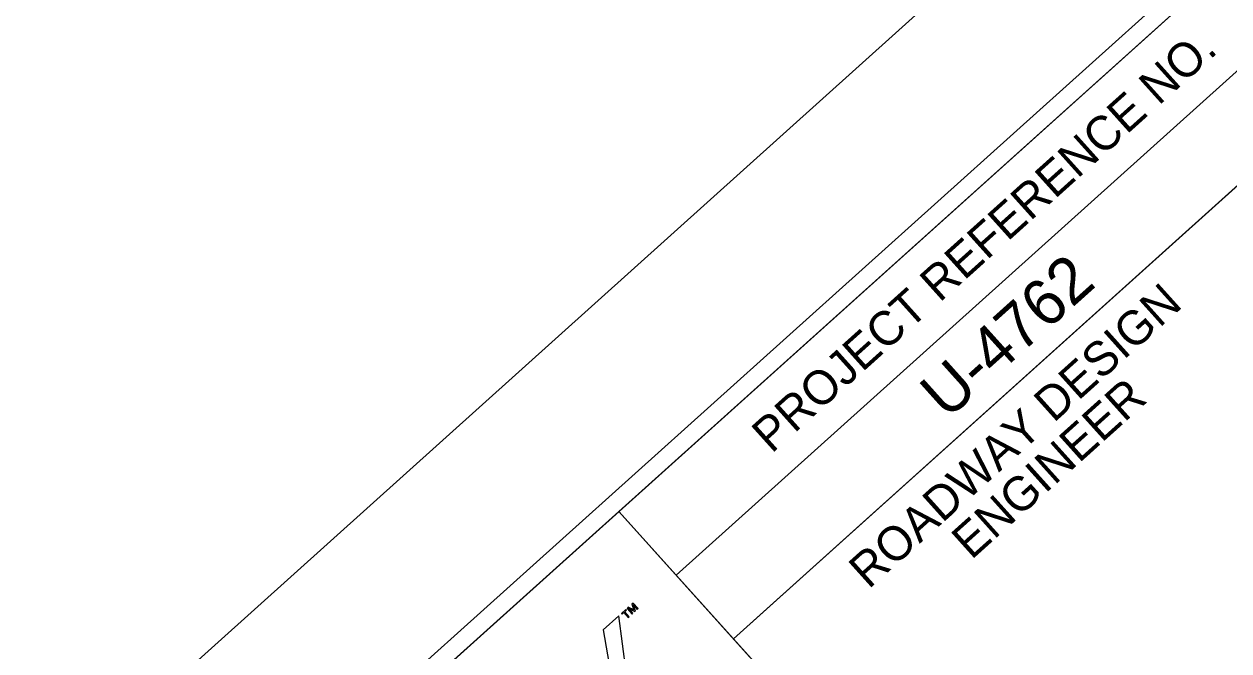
# Model space of a CAD drawing. Extents: x 2488411 to 2488707, y 383669 to 383962.
# Drawn here: x 2488591.42 to 2488612.58, y 383939.51 to 383950.52 of the extents above; entities that cross this region are included whole.
import ezdxf

# ---------------------------------------------------------------- set-up
doc = ezdxf.new("R2010")
doc.units = 0
for name, color, linetype in [('Old_Level_19', 7, 'Continuous'), ('Old_Level_21', 7, 'Continuous'), ('Prop XS SE Text', 7, 'Continuous'), ('Sheet Cutting Line CELL', 7, 'Continuous'), ('Sheet Plot Border Outside CELL', 7, 'Continuous'), ('Sheet Profile CELL', 7, 'Continuous'), ('Sheet Title CELL', 7, 'Continuous')]:
    doc.layers.add(name, color=color, linetype=linetype)

msp = doc.modelspace()

# ---------------------------------------------------------------- linework, layer by layer
at = {"layer": 'Old_Level_19'}
msp.add_lwpolyline([(2488619.231, 383961.604), (2488468.948, 383826.508), (2488557.194, 383728.341), (2488707.477, 383863.438)], close=True, dxfattribs=at)
at = {"layer": 'Old_Level_21'}
msp.add_lwpolyline([(2488620.631, 383959.24), (2488471.909, 383825.547), (2488556.553, 383731.388), (2488705.275, 383865.081)], close=True, dxfattribs=at)
at = {"layer": 'Prop XS SE Text'}
msp.add_line((2488619.231, 383961.604), (2488468.948, 383826.508), dxfattribs=at)
at = {"layer": 'Sheet Cutting Line CELL'}
msp.add_line((2488602.874, 383940.841), (2488620.726, 383956.89), dxfattribs=at)
for points in [[(2488619.72, 383958.009), (2488485.857, 383837.674), (2488570.092, 383743.97), (2488703.955, 383864.305)], [(2488601.867, 383941.961), (2488619.72, 383958.009), (2488621.729, 383955.774), (2488603.876, 383939.725)], [(2488603.876, 383939.725), (2488612.805, 383947.752), (2488621.83, 383937.712), (2488612.902, 383929.685)]]:
    msp.add_lwpolyline(points, close=True, dxfattribs=at)
at = {"layer": 'Sheet Profile CELL'}
for p, q in [((2488601.988, 383940.24), (2488601.909, 383940.169)), ((2488602, 383940.227), (2488601.988, 383940.24)), ((2488602.031, 383940.278), (2488602.009, 383940.258)), ((2488602.009, 383940.258), (2488602.097, 383940.16)), ((2488602.13, 383940.231), (2488602.031, 383940.278)), ((2488602.038, 383940.256), (2488602.037, 383940.256)), ((2488602.112, 383940.173), (2488602.038, 383940.256)), ((2488602.038, 383940.256), (2488602.145, 383940.203)), ((2488602.114, 383940.353), (2488602.093, 383940.334)), ((2488602.093, 383940.334), (2488602.13, 383940.231)), ((2488602.203, 383940.255), (2488602.114, 383940.353)), ((2488602.114, 383940.325), (2488602.114, 383940.324)), ((2488602.155, 383940.211), (2488602.114, 383940.325)), ((2488602.114, 383940.325), (2488602.188, 383940.242)), ((2488602.188, 383940.242), (2488602.203, 383940.255)), ((2488602.203, 383940.255), (2488602.203, 383940.255)), ((2488601.909, 383940.169), (2488601.921, 383940.156)), ((2488601.921, 383940.156), (2488601.954, 383940.185)), ((2488601.954, 383940.185), (2488602.031, 383940.1)), ((2488601.968, 383940.198), (2488602, 383940.227)), ((2488602.045, 383940.113), (2488601.968, 383940.198)), ((2488602, 383940.227), (2488602, 383940.227)), ((2488602.031, 383940.1), (2488602.045, 383940.113)), ((2488602.097, 383940.16), (2488602.112, 383940.173)), ((2488602.145, 383940.203), (2488602.155, 383940.211))]:
    msp.add_line(p, q, dxfattribs=at)
msp.add_lwpolyline([(2488601.823, 383937.784), (2488602.097, 383938.031), (2488601.947, 383938.871), (2488602.769, 383938.635), (2488603.057, 383938.894), (2488601.995, 383939.145), (2488601.865, 383940.13), (2488601.589, 383939.882), (2488601.716, 383939.142), (2488600.991, 383939.344), (2488600.704, 383939.086), (2488601.677, 383938.86), (2488601.823, 383937.784)], dxfattribs=at)
at = {"layer": 'Sheet Title CELL'}
msp.add_lwpolyline([(2488601.867, 383941.961), (2488592.478, 383933.521), (2488599.464, 383925.75), (2488608.852, 383934.19)], close=True, dxfattribs=at)

# ---------------------------------------------------------------- texts
at = {"layer": 'Sheet Cutting Line CELL'}
for s, height, p in [('PROJECT REFERENCE NO.', 0.60001, (2488604.546, 383942.965)), ('ROADWAY DESIGN', 0.60001, (2488606.25, 383940.585)), ('ENGINEER', 0.6, (2488608.054, 383941.1))]:
    msp.add_text(s, height=height, rotation=41.9538, dxfattribs=at).set_placement(p)
at = {"layer": 'Sheet Plot Border Outside CELL'}
msp.add_text('U-4762', height=0.81, rotation=41.9538, dxfattribs=at).set_placement((2488607.627, 383943.556))

doc.saveas('drawing.dxf')
